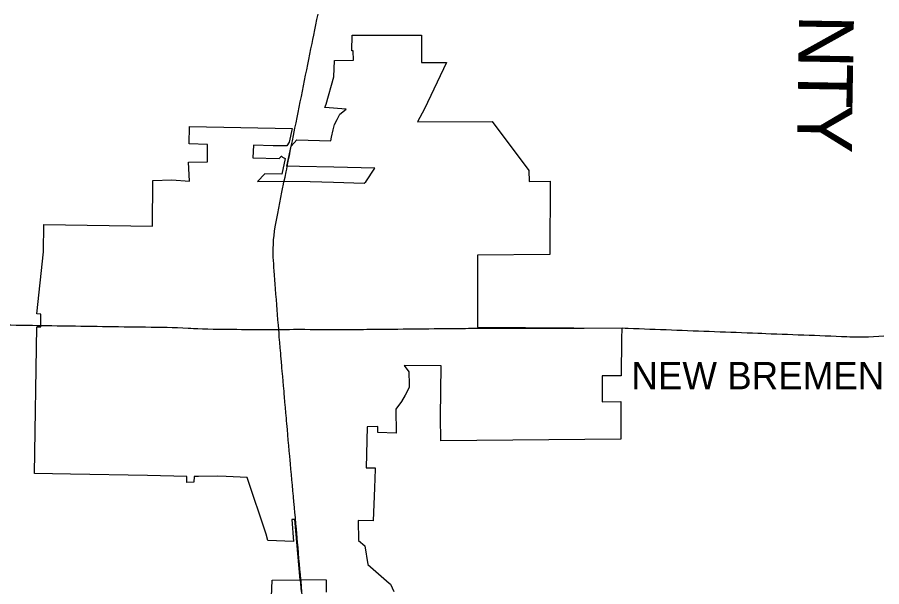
# Model space of a CAD drawing. Extents: x 0 to 34, y 0 to 22.
# Drawn here: x 4.4554 to 4.7085, y 19.0756 to 19.2422 of the extents above; entities that cross this region are included whole.
import ezdxf

# ---------------------------------------------------------------- set-up
doc = ezdxf.new("R2010")
doc.units = 0
for name, color, linetype in [('GM_X_Corporation', 7, 'Continuous'), ('GM_X_Corporation_Text', 7, 'Continuous'), ('GM_X_County_Text', 7, 'Continuous'), ('GM_X_State_Route', 7, 'Continuous')]:
    doc.layers.add(name, color=color, linetype=linetype)

msp = doc.modelspace()

# ---------------------------------------------------------------- linework, layer by layer
at = {"layer": 'GM_X_Corporation'}
for points in [[(4.545888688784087, 19.074012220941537), (4.545891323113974, 19.077526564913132), (4.538201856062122, 19.077551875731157), (4.536607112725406, 19.095245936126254), (4.5357438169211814, 19.095249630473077), (4.536203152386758, 19.088831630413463), (4.528687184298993, 19.089085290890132), (4.528198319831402, 19.09096217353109), (4.522643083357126, 19.107485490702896), (4.516557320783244, 19.107806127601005), (4.513925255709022, 19.107892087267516), (4.508438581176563, 19.10779241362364), (4.507131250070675, 19.107820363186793), (4.507102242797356, 19.10612911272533), (4.5050128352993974, 19.106092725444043), (4.505059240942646, 19.107864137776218), (4.493505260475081, 19.108091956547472), (4.470982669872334, 19.10848800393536), (4.460421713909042, 19.10866678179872), (4.461096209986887, 19.151663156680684), (4.4623017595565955, 19.15164153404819), (4.462296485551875, 19.155366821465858), (4.461090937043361, 19.155387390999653), (4.463019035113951, 19.17355129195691), (4.463171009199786, 19.18160970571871), (4.494937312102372, 19.18107868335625), (4.495073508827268, 19.194451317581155), (4.500648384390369, 19.194593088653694), (4.505755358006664, 19.194291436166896), (4.505515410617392, 19.199821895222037), (4.511067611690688, 19.19990009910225), (4.511117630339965, 19.204966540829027), (4.5057042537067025, 19.205172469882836), (4.50580428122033, 19.210205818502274), (4.535814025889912, 19.209618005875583), (4.535000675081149, 19.205630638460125), (4.5343082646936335, 19.20456474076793), (4.530310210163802, 19.20463888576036), (4.524498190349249, 19.20474722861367), (4.524389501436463, 19.201034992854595), (4.532044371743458, 19.20084022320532), (4.532639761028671, 19.201483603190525), (4.532679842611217, 19.201527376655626), (4.532693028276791, 19.201541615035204), (4.532700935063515, 19.201550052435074), (4.533072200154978, 19.201241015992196), (4.533806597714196, 19.20089897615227), (4.532833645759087, 19.196311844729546), (4.527816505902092, 19.196393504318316), (4.525675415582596, 19.1941617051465), (4.5334665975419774, 19.194269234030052), (4.5411140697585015, 19.194107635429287), (4.547965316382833, 19.193962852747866), (4.556894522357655, 19.193699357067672), (4.557417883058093, 19.19403988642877), (4.560078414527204, 19.1980101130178), (4.548014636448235, 19.1983661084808), (4.537991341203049, 19.198538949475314), (4.534344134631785, 19.198601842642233), (4.535540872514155, 19.204510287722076), (4.537211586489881, 19.206363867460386), (4.547177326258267, 19.20608850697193), (4.547396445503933, 19.207159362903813), (4.547827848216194, 19.209265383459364), (4.548247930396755, 19.210845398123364), (4.549027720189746, 19.21229655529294), (4.549859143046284, 19.213843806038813), (4.551629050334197, 19.21534276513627), (4.545399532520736, 19.21575988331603), (4.545807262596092, 19.216756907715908), (4.548081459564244, 19.22482624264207), (4.54829278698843, 19.229603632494), (4.548364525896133, 19.229603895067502), (4.5538610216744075, 19.22962441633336), (4.553745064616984, 19.2324356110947), (4.553323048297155, 19.232434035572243), (4.553462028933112, 19.236933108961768), (4.573744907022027, 19.237008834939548), (4.573775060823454, 19.22893078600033), (4.578720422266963, 19.228949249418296), (4.58106872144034, 19.2289353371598), (4.574569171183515, 19.21546514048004), (4.572523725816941, 19.211597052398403), (4.594466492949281, 19.211748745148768), (4.605187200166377, 19.197324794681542), (4.605221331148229, 19.194189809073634), (4.611377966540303, 19.194256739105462), (4.611285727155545, 19.17276221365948), (4.590159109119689, 19.17262762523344), (4.590125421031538, 19.151480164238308), (4.6323808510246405, 19.151230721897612), (4.632317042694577, 19.148064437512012), (4.632203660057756, 19.137315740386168), (4.6266046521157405, 19.13723769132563), (4.626615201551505, 19.129654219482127), (4.632132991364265, 19.12974914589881), (4.632070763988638, 19.125449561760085), (4.6320660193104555, 19.118762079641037), (4.579369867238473, 19.11826055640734), (4.579312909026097, 19.125264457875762), (4.579444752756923, 19.14018669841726), (4.568675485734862, 19.14029111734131), (4.5700455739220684, 19.138466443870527), (4.570126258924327, 19.1347807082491), (4.5701141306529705, 19.133843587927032), (4.56892018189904, 19.131598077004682), (4.567828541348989, 19.129770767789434), (4.566246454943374, 19.127498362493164), (4.566286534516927, 19.120542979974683), (4.560953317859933, 19.12072966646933), (4.560953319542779, 19.122433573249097), (4.557827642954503, 19.122378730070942), (4.55757106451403, 19.11036790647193), (4.560125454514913, 19.11037385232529), (4.560114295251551, 19.110005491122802), (4.559996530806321, 19.104503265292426), (4.5596227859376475, 19.094876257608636), (4.555195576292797, 19.094951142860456), (4.555303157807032, 19.08911851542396), (4.557157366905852, 19.087577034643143), (4.55804438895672, 19.082053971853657), (4.564302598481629, 19.07657414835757), (4.564634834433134, 19.07628251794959), (4.565660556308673, 19.074154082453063)], [(4.529557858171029, 19.065196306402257), (4.530011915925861, 19.07752920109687), (4.538201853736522, 19.07753552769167), (4.538503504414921, 19.074200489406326)]]:
    msp.add_lwpolyline(points, dxfattribs=at)
at = {"layer": 'GM_X_State_Route'}
for p, q in [((4.533260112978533, 19.19290034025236), (4.533465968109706, 19.193916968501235)), ((4.462717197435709, 19.152016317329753), (4.463862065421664, 19.15199958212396)), ((4.528675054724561, 19.150822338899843), (4.531913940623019, 19.150829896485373)), ((4.5373123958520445, 19.08996250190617), (4.537219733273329, 19.09100487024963))]:
    msp.add_line(p, q, dxfattribs=at)
for points in [[(4.542165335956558, 19.23694023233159), (4.542480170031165, 19.2384906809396), (4.542795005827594, 19.24004112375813), (4.543109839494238, 19.241591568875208), (4.543424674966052, 19.243142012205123)], [(4.5356070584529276, 19.204482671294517), (4.535920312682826, 19.206033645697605), (4.536233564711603, 19.20758461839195), (4.5364513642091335, 19.20866254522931), (4.536669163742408, 19.209739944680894), (4.536982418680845, 19.21129091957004), (4.537295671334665, 19.212841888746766), (4.537608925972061, 19.214392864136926), (4.537922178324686, 19.215943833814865), (4.538235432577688, 19.217494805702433), (4.5385486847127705, 19.219045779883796), (4.538861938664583, 19.220596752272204), (4.539175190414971, 19.22214772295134), (4.539488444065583, 19.223698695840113), (4.539801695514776, 19.225249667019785), (4.540115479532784, 19.22680064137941), (4.540428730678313, 19.2283516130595), (4.540742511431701, 19.229902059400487), (4.5410557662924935, 19.231453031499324), (4.541369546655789, 19.23300347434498), (4.541682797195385, 19.234554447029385), (4.54192432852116, 19.235747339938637), (4.542165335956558, 19.23694023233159)], [(4.53440888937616, 19.198569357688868), (4.534723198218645, 19.2001198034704), (4.535037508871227, 19.20167024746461), (4.535322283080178, 19.20307619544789), (4.5356070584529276, 19.204482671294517)], [(4.533465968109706, 19.193916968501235), (4.533780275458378, 19.19546741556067), (4.5340945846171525, 19.197017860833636), (4.534251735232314, 19.197793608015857), (4.53440888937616, 19.198569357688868)], [(4.530785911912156, 19.165414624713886), (4.530685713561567, 19.166710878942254), (4.530585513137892, 19.168006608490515), (4.530516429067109, 19.169009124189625), (4.5304468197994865, 19.17001111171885), (4.530391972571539, 19.171014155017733), (4.530337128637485, 19.172017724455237), (4.530310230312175, 19.173288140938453), (4.5303186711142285, 19.174559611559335), (4.530361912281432, 19.175830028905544), (4.530440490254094, 19.177098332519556), (4.530553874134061, 19.178364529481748), (4.530702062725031, 19.179627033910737), (4.53088505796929, 19.180884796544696), (4.531062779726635, 19.18187359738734), (4.531241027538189, 19.18286240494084), (4.531433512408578, 19.18384857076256), (4.531625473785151, 19.18483473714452), (4.5319397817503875, 19.186385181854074), (4.532254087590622, 19.18793562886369), (4.53256839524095, 19.189486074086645), (4.532882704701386, 19.19103651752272), (4.5331743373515, 19.192476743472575), (4.533260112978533, 19.19290034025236)], [(4.53135862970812, 19.158011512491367), (4.531236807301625, 19.159588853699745), (4.5311149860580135, 19.16116619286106), (4.5309926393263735, 19.162743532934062), (4.5308892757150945, 19.164078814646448), (4.530785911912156, 19.165414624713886)], [(4.531913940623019, 19.150829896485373), (4.531816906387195, 19.152084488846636), (4.5316950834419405, 19.153661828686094), (4.531573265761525, 19.155239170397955), (4.531466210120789, 19.156625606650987), (4.53135862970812, 19.158011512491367)], [(4.4450441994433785, 19.152313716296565), (4.445571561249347, 19.152304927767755), (4.447153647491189, 19.152278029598), (4.448735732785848, 19.152251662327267), (4.4503178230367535, 19.152224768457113), (4.451899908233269, 19.152198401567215), (4.453481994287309, 19.152171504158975), (4.455064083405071, 19.152145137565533), (4.456646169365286, 19.15211824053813), (4.458228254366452, 19.15209187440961), (4.459810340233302, 19.1520649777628), (4.461223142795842, 19.152041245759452), (4.462635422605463, 19.152017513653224), (4.462717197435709, 19.152016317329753)], [(4.463862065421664, 19.15199958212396), (4.465444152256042, 19.15197638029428), (4.467026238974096, 19.1519531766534), (4.468608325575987, 19.15192997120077), (4.47019041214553, 19.15190676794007), (4.471290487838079, 19.15189042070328), (4.472390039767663, 19.151874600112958), (4.473972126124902, 19.151851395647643), (4.4755542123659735, 19.151828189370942), (4.477136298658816, 19.15180498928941), (4.478718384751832, 19.15178178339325), (4.4803004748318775, 19.151758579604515), (4.4815494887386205, 19.151740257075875)], [(4.4815494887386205, 19.151740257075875), (4.481882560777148, 19.151735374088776), (4.48346464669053, 19.151712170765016), (4.485046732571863, 19.151688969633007), (4.486628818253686, 19.151665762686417), (4.488210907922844, 19.151642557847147), (4.489792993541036, 19.15161935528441), (4.491375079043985, 19.15159615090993), (4.4929571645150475, 19.15157294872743), (4.494539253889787, 19.15154974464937), (4.496121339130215, 19.151526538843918), (4.497703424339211, 19.151503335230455), (4.499285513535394, 19.151480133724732), (4.500771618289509, 19.15145851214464), (4.502258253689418, 19.151436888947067), (4.5038377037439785, 19.151347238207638), (4.505417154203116, 19.15125758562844), (4.506165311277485, 19.15121511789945)], [(4.506165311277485, 19.15121511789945), (4.506996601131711, 19.15116793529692), (4.50828072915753, 19.151095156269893), (4.509564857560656, 19.15102238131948), (4.511146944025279, 19.151002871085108), (4.512729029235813, 19.15098388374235), (4.513954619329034, 19.150969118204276), (4.5151796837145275, 19.150953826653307)], [(4.5151796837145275, 19.150953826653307), (4.516761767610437, 19.150935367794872), (4.518343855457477, 19.150916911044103), (4.51967281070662, 19.150901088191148), (4.521001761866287, 19.150885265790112), (4.521834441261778, 19.1508755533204)], [(4.521834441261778, 19.1508755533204), (4.52258384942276, 19.15086680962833), (4.524165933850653, 19.150847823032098), (4.525440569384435, 19.15083305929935), (4.526714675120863, 19.150817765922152), (4.528675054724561, 19.150822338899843)], [(4.531913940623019, 19.150829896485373), (4.533496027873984, 19.15085415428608), (4.535078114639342, 19.150878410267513), (4.536275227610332, 19.150896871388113), (4.537471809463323, 19.15091532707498), (4.537973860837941, 19.150909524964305), (4.5387232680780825, 19.150900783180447)], [(4.532577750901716, 19.143073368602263), (4.532506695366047, 19.143902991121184), (4.53237169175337, 19.145479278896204), (4.53223668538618, 19.147055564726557), (4.53210168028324, 19.148631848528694), (4.53200781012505, 19.149730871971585), (4.531913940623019, 19.150829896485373)], [(4.5387232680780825, 19.150900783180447), (4.539555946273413, 19.15089106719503), (4.541138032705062, 19.15087208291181), (4.542369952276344, 19.150857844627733), (4.543601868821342, 19.150843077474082), (4.545183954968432, 19.15082409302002), (4.5463552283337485, 19.150809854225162), (4.547526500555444, 19.15079614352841), (4.549108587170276, 19.15081143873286), (4.550045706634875, 19.15082092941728), (4.5509828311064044, 19.15082989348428), (4.55256491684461, 19.15084518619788), (4.554147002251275, 19.150860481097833), (4.555729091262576, 19.150875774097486), (4.5567279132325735, 19.150885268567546), (4.557726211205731, 19.15089528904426), (4.559308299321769, 19.150910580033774), (4.560246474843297, 19.150920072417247), (4.561184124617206, 19.150929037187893)], [(4.561184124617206, 19.150929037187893), (4.562766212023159, 19.150944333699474), (4.563998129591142, 19.150956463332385), (4.565230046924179, 19.150968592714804), (4.566812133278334, 19.150983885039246), (4.568394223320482, 19.150999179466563), (4.569976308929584, 19.151014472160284), (4.571323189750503, 19.151027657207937), (4.572670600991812, 19.151040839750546), (4.574252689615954, 19.151056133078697), (4.5758347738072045, 19.151071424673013), (4.577416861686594, 19.15108671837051), (4.578902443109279, 19.151101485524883), (4.5803874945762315, 19.151115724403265), (4.581440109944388, 19.15112574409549), (4.582492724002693, 19.151136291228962), (4.584074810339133, 19.151151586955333), (4.585656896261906, 19.15116688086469), (4.586566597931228, 19.15117584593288), (4.5874762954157, 19.151184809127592), (4.588754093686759, 19.151196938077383), (4.590053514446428, 19.151209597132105), (4.621387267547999, 19.151270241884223), (4.632484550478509, 19.15129186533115)], [(4.632484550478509, 19.15129186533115), (4.633374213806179, 19.151257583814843), (4.634264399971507, 19.15122330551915), (4.6358454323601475, 19.151162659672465), (4.637426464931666, 19.15110201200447), (4.639007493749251, 19.15104136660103), (4.640588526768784, 19.15098071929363), (4.6421695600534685, 19.150920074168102), (4.643750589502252, 19.15085942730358), (4.645331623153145, 19.150798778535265), (4.646912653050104, 19.15073813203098), (4.648493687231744, 19.15067748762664), (4.6500747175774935, 19.150616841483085), (4.651655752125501, 19.15055619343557), (4.653236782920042, 19.150495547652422), (4.654817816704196, 19.150435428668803), (4.656398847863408, 19.150374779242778), (4.6579798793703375, 19.150314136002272), (4.65956090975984, 19.150254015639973), (4.661141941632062, 19.150193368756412), (4.662722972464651, 19.150133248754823), (4.66430400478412, 19.150072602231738), (4.665885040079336, 19.150012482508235), (4.667466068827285, 19.14995183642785), (4.669047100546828, 19.149891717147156), (4.670628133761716, 19.149831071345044), (4.672209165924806, 19.149770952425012), (4.673382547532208, 19.149726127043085), (4.6745553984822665, 19.149681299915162), (4.676136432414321, 19.149620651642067), (4.677717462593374, 19.14956000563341), (4.679298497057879, 19.149499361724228), (4.680879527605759, 19.149438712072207), (4.682460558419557, 19.149378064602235), (4.684041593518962, 19.149317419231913), (4.685622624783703, 19.149256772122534), (4.687203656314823, 19.14919612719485), (4.68878468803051, 19.14913548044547), (4.69036571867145, 19.149075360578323), (4.691946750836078, 19.149014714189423), (4.693527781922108, 19.14895459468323), (4.695108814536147, 19.148893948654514), (4.696689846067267, 19.148833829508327), (4.698270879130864, 19.14877318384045), (4.699143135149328, 19.148739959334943), (4.7000153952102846, 19.14870673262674), (4.701532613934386, 19.14866770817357), (4.703050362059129, 19.14868458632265), (4.704568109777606, 19.148701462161), (4.706084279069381, 19.148774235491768), (4.707598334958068, 19.148884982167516), (4.709108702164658, 19.14903317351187)], [(4.532877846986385, 19.139613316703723), (4.532827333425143, 19.140194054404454), (4.532734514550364, 19.141260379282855), (4.532641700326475, 19.14232670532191), (4.532577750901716, 19.143073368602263)], [(4.5342249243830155, 19.1241296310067), (4.534159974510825, 19.124876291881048), (4.534022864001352, 19.126452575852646), (4.533885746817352, 19.12802886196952), (4.533748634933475, 19.129605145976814), (4.533611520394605, 19.131181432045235), (4.533540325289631, 19.131997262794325), (4.5334691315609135, 19.1328125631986), (4.533332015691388, 19.1343888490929), (4.533217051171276, 19.135715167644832), (4.5331015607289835, 19.137041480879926), (4.532964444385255, 19.13861776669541), (4.532877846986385, 19.139613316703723)], [(4.536249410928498, 19.10175987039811), (4.536219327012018, 19.102091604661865), (4.536076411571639, 19.103667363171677), (4.535933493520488, 19.105243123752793), (4.5357905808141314, 19.106818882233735), (4.535647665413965, 19.108394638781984), (4.535505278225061, 19.1099703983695), (4.535362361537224, 19.11154615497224), (4.535263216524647, 19.112642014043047), (4.535164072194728, 19.113737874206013), (4.535021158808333, 19.11531363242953), (4.534878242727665, 19.116889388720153), (4.534735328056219, 19.1184651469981), (4.534592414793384, 19.12004090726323), (4.534449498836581, 19.12161666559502), (4.5343735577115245, 19.12245833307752), (4.5342970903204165, 19.123300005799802), (4.5342249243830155, 19.1241296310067)], [(4.53670585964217, 19.096722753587), (4.536660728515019, 19.09722036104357), (4.536517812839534, 19.09879611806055), (4.536439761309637, 19.09965572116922), (4.536362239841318, 19.100515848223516), (4.536249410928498, 19.10175987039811)], [(4.537219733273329, 19.09100487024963), (4.5370831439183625, 19.092536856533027), (4.536946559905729, 19.094068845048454), (4.536803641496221, 19.09564460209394), (4.53670585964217, 19.096722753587)], [(4.538302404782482, 19.078870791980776), (4.538280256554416, 19.079118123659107), (4.5381394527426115, 19.080693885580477), (4.537998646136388, 19.082269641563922), (4.537858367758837, 19.083845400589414), (4.537717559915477, 19.0854211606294), (4.537577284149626, 19.08699691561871), (4.537436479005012, 19.088572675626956), (4.537327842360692, 19.08978877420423), (4.5373123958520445, 19.08996250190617)], [(4.539462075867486, 19.06535080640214), (4.539358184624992, 19.066668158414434), (4.5392690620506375, 19.067983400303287), (4.5391614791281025, 19.0692975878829), (4.5390201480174, 19.070873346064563), (4.538878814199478, 19.07244910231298), (4.538737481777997, 19.07402486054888), (4.538596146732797, 19.07560062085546), (4.538454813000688, 19.077176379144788), (4.538378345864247, 19.07802332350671), (4.538302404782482, 19.078870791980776)]]:
    msp.add_lwpolyline(points, dxfattribs=at)

# ---------------------------------------------------------------- texts
at = {"layer": 'GM_X_Corporation_Text'}
msp.add_text('NEW BREMEN', height=0.008037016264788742, rotation=1.0000000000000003e-05, dxfattribs=at).set_placement((4.63518254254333, 19.133330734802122))
at = {"layer": 'GM_X_County_Text'}
for s, height, rotation, p in [('N', 0.016074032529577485, 269.028908, (4.684281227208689, 19.243048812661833)), ('T', 0.016074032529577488, 269.040833, (4.684040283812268, 19.228834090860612)), ('Y', 0.016074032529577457, 269.406265, (4.683838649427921, 19.216785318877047))]:
    msp.add_text(s, height=height, rotation=rotation, dxfattribs=at).set_placement(p)

doc.saveas('drawing.dxf')
